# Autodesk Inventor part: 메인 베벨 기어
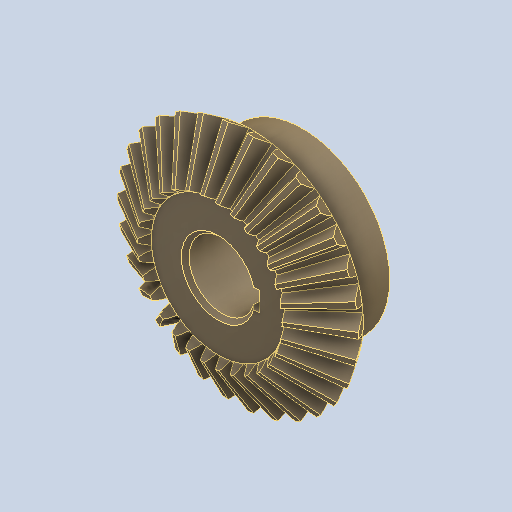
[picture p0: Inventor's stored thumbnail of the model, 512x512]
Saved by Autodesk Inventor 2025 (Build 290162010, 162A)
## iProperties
Created: 2024-07
Part Number: 메인 베벨 기어
Material: 강철, 탄소
Document SubType Name: Modeling
Designer: 학생
Density: 7.87 g/cm^3
Appearance: 기본값
Author: jhkim
Revision Number: 1
Sending System: Autodesk Inventor 2025
Preprocessor: ST-DEVELOPER v20
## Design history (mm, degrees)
feature "Solid1"
node "솔리드1"
